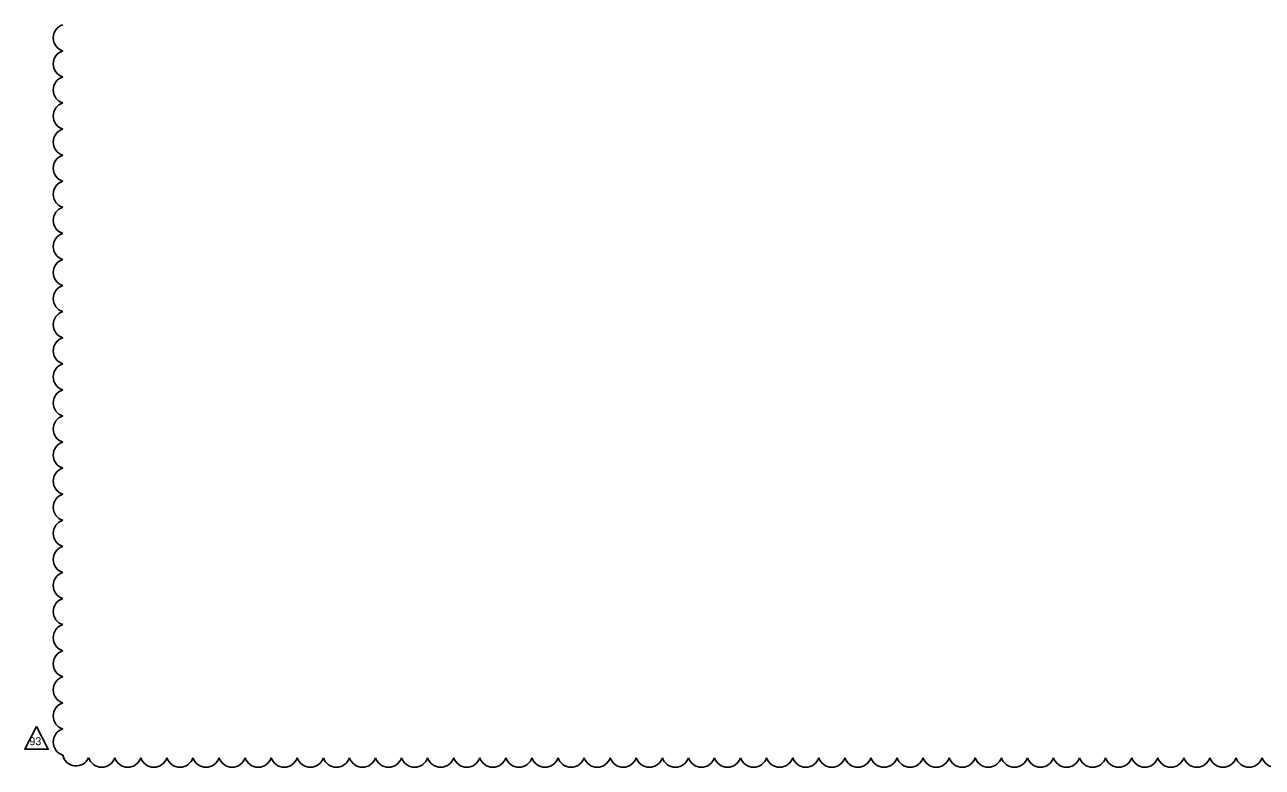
# Model space of a CAD drawing. Extents: x -811 to 10319, y -2309 to 9962.
# Drawn here: x -811.04 to -802.91, y -2229.34 to -2224.47 of the extents above; entities that cross this region are included whole.
import ezdxf

# ---------------------------------------------------------------- set-up
doc = ezdxf.new("R2010")
doc.units = 0
doc.layers.add('TextMisc', color=7, linetype='Continuous')
doc.layers.add('TextTitle', color=7, linetype='Continuous')

msp = doc.modelspace()

# ---------------------------------------------------------------- linework, layer by layer
at = {"layer": 'TextMisc'}
msp.add_lwpolyline([(-810.9581, -2229.0764), (-811.0351, -2229.2247), (-810.8811, -2229.2247)], close=True, dxfattribs=at)
at = {"layer": 'TextTitle'}
for centre, radius, start, end in [((-810.7588, -2224.557), 0.0897, 107.5, 252.5), ((-810.7588, -2224.7281), 0.0897, 107.5, 252.5), ((-810.7588, -2224.8992), 0.0897, 107.5, 252.5), ((-810.7588, -2225.0703), 0.0897, 107.5, 252.5), ((-810.7588, -2225.2415), 0.0897, 107.5, 252.5), ((-810.7588, -2225.4126), 0.0897, 107.5, 252.5), ((-810.7588, -2225.5837), 0.0897, 107.5, 252.5), ((-810.7588, -2225.7548), 0.0897, 107.5, 252.5), ((-810.7588, -2225.926), 0.0897, 107.5, 252.5), ((-810.7588, -2226.0971), 0.0897, 107.5, 252.5), ((-810.7588, -2226.2682), 0.0897, 107.5, 252.5), ((-810.7588, -2226.4393), 0.0897, 107.5, 252.5), ((-810.7588, -2226.6104), 0.0897, 107.5, 252.5), ((-810.7588, -2226.7816), 0.0897, 107.5, 252.5), ((-810.7588, -2226.9527), 0.0897, 107.5, 252.5), ((-810.7588, -2227.1238), 0.0897, 107.5, 252.5), ((-810.7588, -2227.2949), 0.0897, 107.5, 252.5), ((-810.7588, -2227.4661), 0.0897, 107.5, 252.5), ((-810.7588, -2227.6372), 0.0897, 107.5, 252.5), ((-810.7588, -2227.8083), 0.0897, 107.5, 252.5), ((-810.7588, -2227.9794), 0.0897, 107.5, 252.5), ((-810.7588, -2228.1505), 0.0897, 107.5, 252.5), ((-810.7588, -2228.3217), 0.0897, 107.5, 252.5), ((-810.7588, -2228.4928), 0.0897, 107.5, 252.5), ((-810.7588, -2228.6639), 0.0897, 107.5, 252.5), ((-810.7588, -2228.835), 0.0897, 107.5, 252.5), ((-810.7588, -2229.0062), 0.0897, 107.5, 252.5), ((-810.7588, -2229.1773), 0.0897, 107.5, 252.5), ((-810.698, -2229.2446), 0.0896, 191.74536, 336.74536), ((-810.5301, -2229.253), 0.0897, 197.5, 342.5), ((-810.359, -2229.253), 0.0897, 197.5, 342.5), ((-810.1879, -2229.253), 0.0897, 197.5, 342.5), ((-810.0167, -2229.253), 0.0897, 197.5, 342.5), ((-809.8456, -2229.253), 0.0897, 197.5, 342.5), ((-809.6745, -2229.253), 0.0897, 197.5, 342.5), ((-809.5034, -2229.253), 0.0897, 197.5, 342.5), ((-809.3323, -2229.253), 0.0897, 197.5, 342.5), ((-809.1611, -2229.253), 0.0897, 197.5, 342.5), ((-808.99, -2229.253), 0.0897, 197.5, 342.5), ((-808.8189, -2229.253), 0.0897, 197.5, 342.5), ((-808.6478, -2229.253), 0.0897, 197.5, 342.5), ((-808.4766, -2229.253), 0.0897, 197.5, 342.5), ((-808.3055, -2229.253), 0.0897, 197.5, 342.5), ((-808.1344, -2229.253), 0.0897, 197.5, 342.5), ((-807.9633, -2229.253), 0.0897, 197.5, 342.5), ((-807.7921, -2229.253), 0.0897, 197.5, 342.5), ((-807.621, -2229.253), 0.0897, 197.5, 342.5), ((-807.4499, -2229.253), 0.0897, 197.5, 342.5), ((-807.2788, -2229.253), 0.0897, 197.5, 342.5), ((-807.1077, -2229.253), 0.0897, 197.5, 342.5), ((-806.9365, -2229.253), 0.0897, 197.5, 342.5), ((-806.7654, -2229.253), 0.0897, 197.5, 342.5), ((-806.5943, -2229.253), 0.0897, 197.5, 342.5), ((-806.4232, -2229.253), 0.0897, 197.5, 342.5), ((-806.252, -2229.253), 0.0897, 197.5, 342.5), ((-806.0809, -2229.253), 0.0897, 197.5, 342.5), ((-805.9098, -2229.253), 0.0897, 197.5, 342.5), ((-805.7387, -2229.253), 0.0897, 197.5, 342.5), ((-805.5676, -2229.253), 0.0897, 197.5, 342.5), ((-805.3964, -2229.253), 0.0897, 197.5, 342.5), ((-805.2253, -2229.253), 0.0897, 197.5, 342.5), ((-805.0542, -2229.253), 0.0897, 197.5, 342.5), ((-804.8831, -2229.253), 0.0897, 197.5, 342.5), ((-804.7119, -2229.253), 0.0897, 197.5, 342.5), ((-804.5408, -2229.253), 0.0897, 197.5, 342.5), ((-804.3697, -2229.253), 0.0897, 197.5, 342.5), ((-804.1986, -2229.253), 0.0897, 197.5, 342.5), ((-804.0275, -2229.253), 0.0897, 197.5, 342.5), ((-803.8563, -2229.253), 0.0897, 197.5, 342.5), ((-803.6852, -2229.253), 0.0897, 197.5, 342.5), ((-803.5141, -2229.253), 0.0897, 197.5, 342.5), ((-803.343, -2229.253), 0.0897, 197.5, 342.5), ((-803.1718, -2229.253), 0.0897, 197.5, 342.5), ((-803.0007, -2229.253), 0.0897, 197.5, 342.5), ((-802.8296, -2229.253), 0.0897, 197.5, 342.5)]:
    msp.add_arc(centre, radius, start, end, dxfattribs=at)

# ---------------------------------------------------------------- texts
at = {"layer": 'TextMisc'}
msp.add_text('93', height=0.0525, rotation=360, dxfattribs=at).set_placement((-811.0047, -2229.1984))

doc.saveas('drawing.dxf')
